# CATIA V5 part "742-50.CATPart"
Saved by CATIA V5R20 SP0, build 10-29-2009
Part number: 742-50
Bounding box of the stored display mesh (mm): x -40 to 40.5, y -40 to 40, z -47 to 80
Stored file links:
  C:\Users\Utente\Desktop\IO LAVORO\3D X SITO CF\X SITO\742\742-50.CATPart
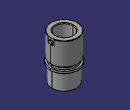
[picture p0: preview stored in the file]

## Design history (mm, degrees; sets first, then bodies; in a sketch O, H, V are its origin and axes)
Set1
  DatumSurface1 to DatumSurface38 "742-50"
Body1 (main body)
